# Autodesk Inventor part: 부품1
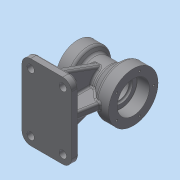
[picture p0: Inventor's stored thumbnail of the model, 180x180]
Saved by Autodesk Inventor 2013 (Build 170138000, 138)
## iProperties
Created: 2015-08
Part Number: 부품1
Material: 일반
Document SubType Name: Modeling
Designer: Administrator
Density: 1 g/cm^3
Author: Administrator
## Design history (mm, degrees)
sketch "스케치1"
  geometry: L1 (0, 0)-(90, 0); L2 (0, 0)-(0, 35); L3 (0, 35)-(20, 35); L4 (20, 35)-(25.196, 26); L5 (25.196, 26)-(53.315, 26); L6 (53.315, 26)-(70, 40); L7 (70, 40)-(90, 40); L8 (90, 40)-(90, 0)
  constraints: 17 end point, 3 parallel, 2 perpendicular, 1 horizontal
  dimensions: "d0" = 90 distance of L1.start L1.end; "d2" = 70 diameter of L3 L1; "d3" = 80 diameter of L7 L1; "d4" = 60 deg angle of L5 L4; "d6" = 40 deg angle of L6 L5; "d7" = 20 distance of L6.end L7.end; "d8" = 20 distance of L2.end L3.end; "d9" = 52 diameter of L5 L1
revolve "회전1" sketch "스케치1" stored, may be unused: angle "d10" = 90 deg
node "작업 평면1"
sketch "스케치2"
  geometry: L1 (0, 61)-(80, 61); L2 (80, 61)-(80, -61); L3 (80, -61)-(0, -61); L4 (0, -61)-(0, 61); 2 further points
  constraints: 8 end point, 2 parallel, 1 coincident, 1 horizontal, 1 midpoint, 1 perpendicular, 1 vertical alignment
  dimensions: "d12" = 80 distance of L1.start L1.end; "d14" = 122 distance of L1.end L2.end
extrude "돌출1" join sketch "스케치2" distance "d15" = 12; taper "d16" = 0 deg
fillet "모깎기1" dims "d17" = 14
node "작업 평면2"
sketch "스케치6"
  geometry: L1 (-90, 61)-(-78, 61) reference; L2 (-78, 61)-(-78, -61) reference; L3 (-78, -61)-(-90, -61) reference; L4 (-90, -61)-(-90, 61) reference; L5 (-78, 51)-(-6.815, 25.091); L6 (-6.815, 25.091)-(-6.815, -25.091); L7 (-6.815, -25.091)-(-78, -51); A1 r 26 centre (0, 0) between (-6.815, 25.091) and (-6.815, -25.091) reference; 1 further point
  constraints: 6 end point, 2 point on circle, 2 point on line, 1 parallel
  dimensions: "d29" = 10 distance of L5.start L1.end; "d30" = 10 distance of L2.end L7.end; "d31" = 70 deg angle of L2 L7
extrude "돌출2" join sketch "스케치6" stored distance "d32" = 12; taper "d33" = 0 deg
sketch "스케치7"
  geometry: L1 (0, -35)-(0, 35) reference; L2 (0, 35)-(20, 35) reference; L3 (20, 35)-(25.196, 26) reference; L4 (25.196, 26)-(53.315, 26) reference; L5 (53.315, 26)-(70, 40) reference; L6 (70, 40)-(90, 40) reference; L7 (90, 40)-(90, -40) reference; L8 (90, -40)-(70, -40) reference; L9 (70, -40)-(53.315, -26) reference; L10 (53.315, -26)-(46, -26) reference; L11 (46, -26)-(46, -78) reference; L12 (46, -78)-(80, -78) reference; L13 (80, -78)-(80, -90) reference; L14 (80, -90)-(0, -90) reference; L15 (0, -90)-(0, -78) reference; L16 (0, -78)-(34, -78) reference; L17 (34, -78)-(34, -26) reference; L18 (34, -26)-(25.196, -26) reference; L19 (25.196, -26)-(20, -35) reference; L20 (20, -35)-(0, -35) reference; L21 (10, -35)-(10, -78); L22 (76.7, -40)-(70, -78); 1 further point
  constraints: 4 end point, 3 point on line, 1 midpoint, 1 perpendicular
  dimensions: "d34" = 10 distance from line of L13 L22.end; "d35" = 80 deg angle of L12 L22; "d36" = 10 distance between parallel lines of L21 L15
  node "절단 모서리 투영2"
feature "리브1" dims "d37" = 1, "d38" = 12, "d39" = 0, "d40" = 0, "d41" = 1, "d42" = 1
feature "리브2" dims "d43" = 1, "d44" = 12, "d45" = 0, "d46" = 0, "d47" = 1, "d48" = 1
sketch "스케치8"
  geometry: L1 (-30, -54)-(-30, -60); L2 (-18, -54)-(-18, -60); L3 (-47, -90)-(47, -90) reference; A1 r 26 centre (0, 0) between (-25.091, -6.815) and (-6, -25.298) reference; A2 r 6 centre (-24, -54) between (-18, -54) and (-30, -54); A3 r 6 centre (-24, -60) between (-30, -60) and (-18, -60)
  constraints: 4 end point, 4 point on circle, 4 tangent, 2 centre point, 1 vertical alignment
  dimensions: "d49" = 12 diameter of A2; "d50" = 12 diameter of A3; "d51" = 18 dimension on A3 A2; "d52" = 24 horizontal distance of A1.centre A3.centre; "d53" = 30 distance from line of L3 A3.centre
extrude "돌출3" cut sketch "스케치8" distance "d54" = 12; taper "d55" = 0 deg
sketch "스케치9"
  geometry: C1 r 6 at (14, -47); C2 r 6 at (66, -47); C3 r 6 at (66, 47); C4 r 6 at (14, 47); A1 r 14 centre (66, 47) between (80, 47) and (66, 61) reference; A2 r 14 centre (14, 47) between (14, 61) and (0, 47) reference; A3 r 14 centre (14, -47) between (0, -47) and (14, -61) reference; A4 r 14 centre (66, -47) between (66, -61) and (80, -47) reference; 1 further point
  constraints: 4 centre point, 4 coincident
  dimensions: "d56" = 12 diameter of C1; "d57" = 12 diameter of C2; "d58" = 12 diameter of C3; "d59" = 12 diameter of C4
extrude "돌출4" cut sketch "스케치9" distance "d60" = 12; taper "d61" = 0 deg
hole "구멍1" diameter "d67" = 38; stored, may be unused: countersink angle "d71" = 90 deg, drill point angle "d73" = 0 deg; dims "d65" = 10, "d66" = 10, "d68" = 6, "d69" = 52, "d70" = 20, "d72" = 23
hole "구멍2" diameter "d76" = 32; stored, may be unused: countersink angle "d80" = 90 deg, drill point angle "d82" = 0 deg; dims "d74" = 10, "d75" = 10, "d77" = 6, "d78" = 40, "d79" = 17, "d81" = 23
sketch "스케치11"
  geometry: C1 r 26 at (0, 0) reference; 1 further point
  constraints: 1 vertical alignment
  dimensions: "d83" = 33 distance of C1.centre point (0, 33)
hole "구멍3" sketch "스케치11" at (0, 33) diameter "d84" = 3.242; stored, may be unused: countersink angle "d88" = 90 deg, drill point angle "d90" = 0 deg; dims "d85" = 10, "d86" = 40, "d87" = 17, "d89" = 13
sketch "스케치12"
  geometry: C1 r 20 at (0, 0) reference; 1 further point
  constraints: 1 vertical alignment
  dimensions: "d94" = 27 distance of point (0, 27) C1.centre
hole "구멍4" sketch "스케치12" at (0, 27) diameter "d95" = 3.242; stored, may be unused: countersink angle "d99" = 90 deg, drill point angle "d101" = 0 deg; dims "d96" = 10, "d97" = 40, "d98" = 17, "d100" = 13
fillet "모깎기2" dims "d105" = 5
fillet "모깎기3" dims "d106" = 0.3
fillet "모깎기4" dims "d107" = 3
fillet "모깎기5" dims "d108" = 3
node "솔리드1"
mirror "대칭1"
pattern_circular "원형 패턴1" dims angle "d92" = 360 deg
pattern_circular "원형 패턴2" dims angle "d103" = 360 deg
node "절단 모서리 투영1"
